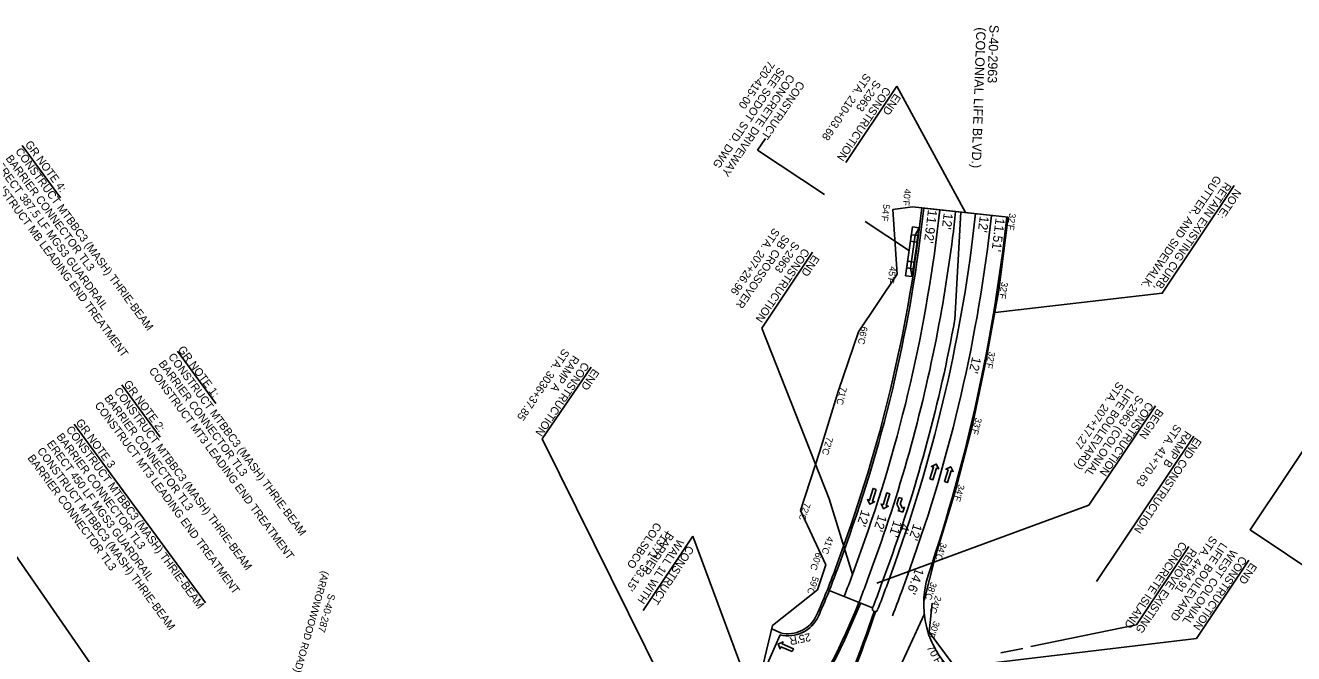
# Model space of a CAD drawing. Extents: x 1966090 to 1975830, y 788086 to 801233.
# Drawn here: x 1971145 to 1972095, y 796534 to 797004 of the extents above; entities that cross this region are included whole.
import ezdxf

# ---------------------------------------------------------------- set-up
doc = ezdxf.new("R2010")
doc.units = 0
for name, color, linetype in [('BR_PROPOSED_DRAINAGE', 7, 'Continuous'), ('BR_SITE LOCATION', 7, 'Continuous'), ('RD_EX_Driveway_txCode', 7, 'Continuous'), ('RD_EX_RW_TX', 7, 'Continuous'), ('RD_EX_SU_Gas', 7, 'Continuous'), ('RD_EX_SU_H2O', 7, 'Continuous'), ('RD_EX_SU_SwpLmt', 7, 'Continuous'), ('RD_EX_Survey_Limits', 7, 'Continuous'), ('RD_EX_TX_Dam_ELEV', 7, 'Continuous'), ('RD_PD_RW_TX', 7, 'Continuous'), ('RD_Sketch6', 7, 'Continuous'), ('RD_Sketch8', 7, 'Continuous')]:
    doc.layers.add(name, color=color, linetype=linetype)

msp = doc.modelspace()

# ---------------------------------------------------------------- linework, layer by layer
at = {"layer": 'BR_PROPOSED_DRAINAGE'}
for p, q in [((1971795.07, 796866.52), (1971809.62, 796868.45)), ((1971798.22, 796817.86), (1971795.07, 796866.52)), ((1971881.34, 796860.66), (1971809.62, 796868.45)), ((1971874.29, 796805.9), (1971880.91, 796856.89)), ((1971880.91, 796856.89), (1971881.34, 796860.65)), ((1971769.18, 796774.78), (1971798.22, 796817.86)), ((1971865.15, 796755.29), (1971874.29, 796805.9)), ((1971753.86, 796730.09), (1971769.18, 796774.78)), ((1971854.62, 796704.93), (1971865.15, 796755.29)), ((1971740.35, 796685.23), (1971753.86, 796730.09)), ((1971841.66, 796655.11), (1971854.62, 796704.93)), ((1971725.72, 796640.78), (1971740.35, 796685.23)), ((1971826.61, 796605.84), (1971841.66, 796655.11)), ((1971725.72, 796640.78), (1971744.84, 796600.07)), ((1971744.84, 796600.07), (1971738.55, 796581.48)), ((1971818.45, 796573.54), (1971826.61, 796605.84)), ((1971704.88, 796554.82), (1971738.55, 796581.48)), ((1971822.14, 796549.74), (1971824.35, 796571.4)), ((1971692.75, 796504.66), (1971704.88, 796554.82)), ((1971850.26, 796511.91), (1971822.14, 796549.74))]:
    msp.add_line(p, q, dxfattribs=at)
at = {"layer": 'BR_SITE LOCATION'}
msp.add_line((1971814.59, 796852.78), (1971811.78, 796847.11), dxfattribs=at)
for points in [[(1971809.63, 796853.47), (1971804.52, 796816.82), (1971809.47, 796816.13), (1971814.59, 796852.78)], [(1971813.76, 796846.83), (1971813.06, 796841.88), (1971808.11, 796842.57), (1971808.8, 796847.53)], [(1971810.99, 796827.03), (1971810.3, 796822.07), (1971805.35, 796822.77), (1971806.04, 796827.72)]]:
    msp.add_lwpolyline(points, close=True, dxfattribs=at)
msp.add_lwpolyline([(1971811.78, 796847.11), (1971808.32, 796822.35), (1971809.47, 796816.13)], dxfattribs=at)
at = {"layer": 'RD_EX_Driveway_txCode'}
for p, q in [((1971799.56, 796650.65), (1971797.97, 796645.54)), ((1971801.85, 796649.94), (1971799.56, 796650.65)), ((1971800.55, 796645.76), (1971801.85, 796649.94)), ((1971797.97, 796645.54), (1971800.06, 796641.58)), ((1971800.06, 796641.58), (1971798.62, 796640.82)), ((1971798.62, 796640.82), (1971802.44, 796639.63)), ((1971802.18, 796642.69), (1971800.55, 796645.76)), ((1971803.63, 796643.45), (1971802.18, 796642.69)), ((1971802.44, 796639.63), (1971803.63, 796643.45))]:
    msp.add_line(p, q, dxfattribs=at)
for points in [[(1971822.75, 796664.6), (1971825.05, 796663.88), (1971827.77, 796672.64), (1971829.33, 796672.16), (1971827.47, 796675.7), (1971823.93, 796673.84), (1971825.48, 796673.35)], [(1971833.63, 796662.54), (1971835.92, 796661.83), (1971838.65, 796670.59), (1971840.2, 796670.1), (1971838.34, 796673.65), (1971834.8, 796671.79), (1971836.35, 796671.3)], [(1971782.44, 796656.65), (1971780.14, 796657.37), (1971777.42, 796648.61), (1971775.86, 796649.09), (1971777.72, 796645.55), (1971781.27, 796647.41), (1971779.71, 796647.9)], [(1971792.72, 796653.27), (1971790.42, 796653.99), (1971787.7, 796645.23), (1971786.14, 796645.71), (1971788, 796642.17), (1971791.54, 796644.03), (1971789.99, 796644.52)], [(1971719.56, 796535.11), (1971720.49, 796537.32), (1971712.02, 796540.85), (1971712.65, 796542.35), (1971708.95, 796540.83), (1971710.47, 796537.13), (1971711.1, 796538.64)]]:
    msp.add_lwpolyline(points, close=True, dxfattribs=at)
at = {"layer": 'RD_EX_SU_Gas'}
for p, q in [((1971770.97, 796610.34), (1971764.69, 796592.91)), ((1971782.26, 796606.27), (1971775.98, 796588.84)), ((1971807.66, 796597.12), (1971801.38, 796579.68)), ((1971779.76, 796567.84), (1971747.27, 796580.84)), ((1971794.68, 796511.27), (1971818.54, 796562.86))]:
    msp.add_line(p, q, dxfattribs=at)
for centre, radius, start, end in [((1970728.29, 796986.16), 1108.34, 340.17915, 353.78725), ((1970728.29, 796986.16), 1147.34, 340.17915, 353.78793), ((1970728.29, 796986.16), 1120.34, 349.70331, 353.78725), ((1970728.29, 796986.16), 1120.34, 340.17915, 349.70331), ((1971283.02, 796766.52), 512, 338.20039, 340.17915), ((1971283.02, 796766.52), 524, 338.20039, 340.17915), ((1971283.02, 796766.52), 524, 327.25584, 338.20039), ((1971284.1, 796765.8), 524, 327.25584, 338.20039), ((1971283.02, 796766.52), 551, 338.20039, 340.17915), ((1971051.22, 796804.85), 768, 334.44688, 341.82587), ((1971051.22, 796804.85), 769, 334.44688, 341.82587)]:
    msp.add_arc(centre, radius, start, end, dxfattribs=at)
at = {"layer": 'RD_EX_Survey_Limits'}
for p, q in [((1971845.85, 796864.5), (1971841.41, 796783.93)), ((1971792.61, 796602.54), (1971786.33, 796585.11)), ((1971796.37, 796601.18), (1971790.09, 796583.75))]:
    msp.add_line(p, q, dxfattribs=at)
for centre, radius, start, end in [((1970728.29, 796986.16), 1135.34, 340.17915, 353.78725), ((1970728.29, 796986.16), 1131.34, 340.17915, 349.70331), ((1971283.02, 796766.52), 535, 338.20039, 340.17915), ((1971283.02, 796766.52), 539, 338.23051, 340.17915), ((1971781.62, 796567.1), 2, 158.20039, 338.20039)]:
    msp.add_arc(centre, radius, start, end, dxfattribs=at)
at = {"layer": 'RD_EX_TX_Dam_ELEV'}
msp.add_line((1971102.57, 796657.26), (1971282.06, 796398.62), dxfattribs=at)
at = {"layer": 'RD_PD_RW_TX'}
for p, q in [((1971758.27, 796614.92), (1971751.99, 796597.49)), ((1971710.76, 796549.19), (1971703.64, 796552.35))]:
    msp.add_line(p, q, dxfattribs=at)
for centre, radius, start, end in [((1970728.29, 796986.16), 1094.84, 340.17915, 353.7876), ((1971283.02, 796766.52), 498.5, 335.82729, 340.17915), ((1971716.37, 796572.01), 23.5, 256.18069, 335.82729)]:
    msp.add_arc(centre, radius, start, end, dxfattribs=at)
at = {"layer": 'RD_Sketch6'}
for p, q in [((1971759.82, 796901.73), (1971797.97, 796958.7)), ((1971142.2, 796914.34), (1971171.1, 796875.13)), ((1971699.54, 796919.63), (1971693.59, 796910.75)), ((1971693.59, 796910.75), (1971743.68, 796877.63)), ((1971774.23, 796857.43), (1971806.81, 796835.89)), ((1971696.67, 796777.54), (1971734.82, 796834.51)), ((1971258.64, 796760.29), (1971287.54, 796721.09)), ((1971532.15, 796694.61), (1971568.79, 796748.33)), ((1971216.95, 796735.08), (1971245.85, 796695.88)), ((1971941.81, 796644.79), (1971991.77, 796719.4)), ((1971181.17, 796705.57), (1971279.85, 796571.71)), ((1971532.15, 796694.61), (1971659.59, 796437.59)), ((1971947.62, 796587.58), (1972020.68, 796696.68)), ((1971941.81, 796644.79), (1971783.04, 796586.3)), ((1971607.82, 796565.9), (1971645.1, 796621.56)), ((1971686.91, 796509.27), (1971645.1, 796621.56)), ((1971977.52, 796555.24), (1972016.85, 796613.96)), ((1972022.56, 796545), (1972061.89, 796603.72)), ((1971977.52, 796555.24), (1971898.49, 796538.85)), ((1972022.56, 796545), (1971872.27, 796526.95)), ((1971892.42, 796537.59), (1971875.83, 796534.15))]:
    msp.add_line(p, q, dxfattribs=at)
for points in [[(1971797.97, 796958.7), (1971849.51, 796864.11), (1971849.51, 796864.11)], [(1972050.94, 796884.42), (1971996.87, 796803.68), (1971871.71, 796789.22)], [(1971696.67, 796777.54), (1971747.35, 796649.56), (1971764.69, 796592.91)]]:
    msp.add_lwpolyline(points, dxfattribs=at)
msp.add_lwpolyline([(1972368.11, 796724.18), (1972228.41, 796515.56), (1972062.74, 796626.5), (1972202.44, 796835.12)], close=True, dxfattribs=at)
at = {"layer": 'RD_Sketch8'}
for p, q in [((1971881.34, 796860.66), (1971818.2, 796867.52)), ((1971759.68, 796614.41), (1971753.4, 796596.98)), ((1971710.41, 796547.73), (1971695.48, 796513.86))]:
    msp.add_line(p, q, dxfattribs=at)
for centre, radius, start, end in [((1970728.29, 796986.16), 1096.34, 340.17915, 353.7876), ((1970607.08, 796999.33), 1280.78, 341.50403, 353.78925), ((1971283.02, 796766.52), 500, 335.82729, 340.17915), ((1971888.09, 796570.81), 70, 161.50403, 237.28747), ((1971716.37, 796572.01), 25, 256.18069, 335.82729)]:
    msp.add_arc(centre, radius, start, end, dxfattribs=at)

# ---------------------------------------------------------------- texts
at = {"layer": 'RD_EX_Driveway_txCode'}
for s, rotation, p in [("11.92'", 262.9248, (1971821.36, 796866.54)), ("12'", 262.9248, (1971833.15, 796864.04)), ("12'", 262.9248, (1971860.17, 796861.75)), ("11.51'", 262.9248, (1971872.06, 796860.28)), ("12'", 257.17368, (1971854.57, 796756.44)), ("12'", 252.06847, (1971771.6, 796641.84)), ("12'", 252.06847, (1971784.18, 796638.08)), ("11'", 252.06847, (1971795.71, 796633.95)), ("4'", 252.06847, (1971801.4, 796631.55)), ("12'", 252.06847, (1971810.58, 796631.39)), ("14.6'", 250.17915, (1971812.03, 796598.42))]:
    msp.add_text(s, height=7, rotation=rotation, dxfattribs=at).set_placement(p)
at = {"layer": 'RD_EX_RW_TX'}
for s, rotation, p in [("40'F", 263.78785, (1971803.67, 796882.09)), ("54'F", 263.60091, (1971787.75, 796870.57)), ("32'F", 263.60091, (1971882.24, 796863.84)), ("45'F", 261.06084, (1971792.74, 796824.15)), ("32'F", 261.06084, (1971876.44, 796812.39)), ("32'F", 258.52077, (1971867.02, 796760.27)), ("33'F", 255.98071, (1971856.94, 796710.78)), ("34'F", 253.44064, (1971844.14, 796660.82)), ("60'C", 250.17915, (1971737.42, 796609.89)), ("34'C", 250.90057, (1971830.94, 796617.27)), ("59'C", 250.17913, (1971735.05, 796591.87)), ("38'C", 250.17915, (1971823.47, 796587.68)), ("24'C", 250.17913, (1971826.96, 796577.44)), ("30'F", 249.20868, (1971825.69, 796558.43))]:
    msp.add_text(s, height=5, rotation=rotation, dxfattribs=at).set_placement(p)
at = {"layer": 'RD_EX_SU_H2O'}
for s, height, rotation, p in [('(COLONIAL LIFE BLVD.)', 7, 267.99519, (1971857.64, 797003.02)), ('S-40-2963', 7, 267.99519, (1971867.45, 797004.85)), ('(ARROWWOOD ROAD)', 5.3996, 254.2312, (1971367.31, 796595.95)), ('S-40-287', 5.4, 254.2312, (1971371.96, 796579.04))]:
    msp.add_text(s, height=height, rotation=rotation, dxfattribs=at).set_placement(p)
at = {"layer": 'RD_EX_SU_SwpLmt'}
for s, rotation, p in [("66'C", 258.52077, (1971771.32, 796779.13)), ("71'C", 255.98071, (1971755.8, 796733.8)), ("72'C", 253.44064, (1971745.55, 796696.35)), ("72'C", 250.90057, (1971728.74, 796647.15)), ("41'C", 250.17915, (1971746.05, 796621.93))]:
    msp.add_text(s, height=5, rotation=rotation, dxfattribs=at).set_placement(p)
at = {"layer": 'RD_Sketch6'}
for s, height, rotation, p in [('SEE SCDOT STD. DWG', 5.9996, 235.85944, (1971709.45, 796973.34)), ('720-415-00', 6, 235.85944, (1971702, 796978.39)), ('CONCRETE DRIVEWAY', 5.9996, 235.85944, (1971716.89, 796968.28)), ('CONSTRUCT', 6, 235.85944, (1971724.34, 796963.23)), ('STA. 210+03.68', 5.9996, 235.85944, (1971774.1, 796968.91)), ('S-2963', 6, 235.85944, (1971781.55, 796963.86)), ('CONSTRUCTION', 5.9996, 235.85944, (1971789, 796958.8)), ('END ', 6, 235.85944, (1971796.45, 796953.75)), ('GR NOTE 4:', 6, 306.42425, (1971144.09, 796915.26)), ('BARRIER CONNECTOR TL3', 5.9996, 306.42425, (1971129.6, 796904.57)), ('CONSTRUCT MTBBC3 (MASH) THRIE-BEAM', 5.9996, 306.42425, (1971136.85, 796909.91)), ('CONSTRUCT MB LEADING END TREATMENT', 5.9996, 306.42425, (1971115.12, 796893.88)), ('ERECT 387.5 LF MGS3 GUARDRAIL', 5.9996, 306.42425, (1971122.36, 796899.23)), ('GUTTER, AND SIDEWALK.', 5.9996, 235.85944, (1972036.76, 796892.48)), ('RETAIN EXISTING CURB, ', 5.9996, 235.85944, (1972044.2, 796887.43)), ('NOTE:', 6, 235.85944, (1972051.65, 796882.38)), ('STA. 207+26.96', 5.9996, 235.85944, (1971705.66, 796853.02)), ('SB CROSSOVER', 5.9996, 235.85944, (1971713.11, 796847.97)), ('CONSTRUCTION', 5.9996, 235.85944, (1971728.01, 796837.87)), ('S-2963', 6, 235.85944, (1971720.56, 796842.92)), ('END ', 6, 235.85944, (1971735.45, 796832.82)), ('GR NOTE 1:', 6, 306.42425, (1971258.71, 796761.47)), ('STA. 3036+37.85', 5.9996, 235.85944, (1971548.06, 796762.71)), ('BARRIER CONNECTOR TL3', 5.9996, 306.42425, (1971244.22, 796750.79)), ('CONSTRUCT MTBBC3 (MASH) THRIE-BEAM', 5.9996, 306.42425, (1971251.47, 796756.13)), ('CONSTRUCTION', 5.9996, 235.85944, (1971562.95, 796752.61)), ('RAMP A', 6, 235.85944, (1971555.5, 796757.66)), ('CONSTRUCT MT3 LEADING END TREATMENT', 5.9996, 306.42425, (1971236.98, 796745.44)), ('END ', 6, 235.85944, (1971570.4, 796747.56)), ('CONSTRUCT MTBBC3 (MASH) THRIE-BEAM', 5.9996, 306.42425, (1971210.81, 796730.39)), ('GR NOTE 2:', 6, 306.42425, (1971218.05, 796735.73)), ('LIFE BOULEVARD)', 5.9996, 235.85944, (1971970.98, 796732.83)), ('STA. 207+17.27', 5.9996, 235.85944, (1971963.53, 796737.88)), ('BARRIER CONNECTOR TL3', 5.9996, 306.42425, (1971203.57, 796725.04)), ('S-2963 (COLONIAL ', 5.9996, 235.85944, (1971978.43, 796727.78)), ('CONSTRUCT MT3 LEADING END TREATMENT', 5.9996, 306.42425, (1971196.33, 796719.7)), ('CONSTRUCTION', 5.9996, 235.85944, (1971985.87, 796722.73)), ('BEGIN ', 6, 235.85944, (1971993.32, 796717.68)), ('CONSTRUCT MTBBC3 (MASH) THRIE-BEAM', 5.9996, 306.42425, (1971174.94, 796701.5)), ('GR NOTE 3', 6, 306.42425, (1971182.18, 796706.84)), ('STA. 41+70.63', 5.9996, 236.35283, (1972006.82, 796706.06)), ('BARRIER CONNECTOR TL3', 5.9996, 306.42425, (1971167.7, 796696.16)), ('END CONSTRUCTION', 5.9996, 236.35283, (1972021.8, 796696.09)), ('RAMP B', 6, 236.35283, (1972014.31, 796701.08)), ('CONSTRUCT MTBBC3 (MASH) THRIE-BEAM', 5.9996, 306.42425, (1971153.22, 796685.47)), ('ERECT 450 LF MGS3 GUARDRAIL', 5.9996, 306.42425, (1971160.46, 796690.81)), ('BARRIER CONNECTOR TL3', 5.9996, 306.42425, (1971145.98, 796680.13)), ('COLSBCO', 6, 236.19133, (1971617.1, 796632.51)), ("+13.71 - 33.15'", 5.9996, 236.19133, (1971624.58, 796627.5)), ('WALL 1L WITH', 5.9996, 236.71509, (1971633.77, 796620.06)), ('BARRIER', 6, 236.71509, (1971626.25, 796625)), ('STA. 4+64.91', 5.9996, 235.85944, (1972033.65, 796622.42)), ('CONSTRUCT', 6, 236.71509, (1971641.3, 796615.12)), ('CONCRETE ISLAND', 5.9996, 235.85944, (1972010.95, 796618.12)), ('REMOVE EXISTING ', 5.9996, 235.85944, (1972018.4, 796613.07)), ('LIFE BOULEVARD', 5.9996, 235.85944, (1972041.1, 796617.36)), ('WEST COLONIAL ', 5.9996, 235.85944, (1972048.55, 796612.31)), ('CONSTRUCTION', 5.9996, 235.85944, (1972055.99, 796607.26)), ('END ', 6, 235.85944, (1972063.44, 796602.21)), ("25'R", 6, 192.10002, (1971732.74, 796549.12)), ("70'R", 6, 298.64948, (1971820.17, 796538.33))]:
    msp.add_text(s, height=height, rotation=rotation, dxfattribs=at).set_placement(p)

doc.saveas('drawing.dxf')
